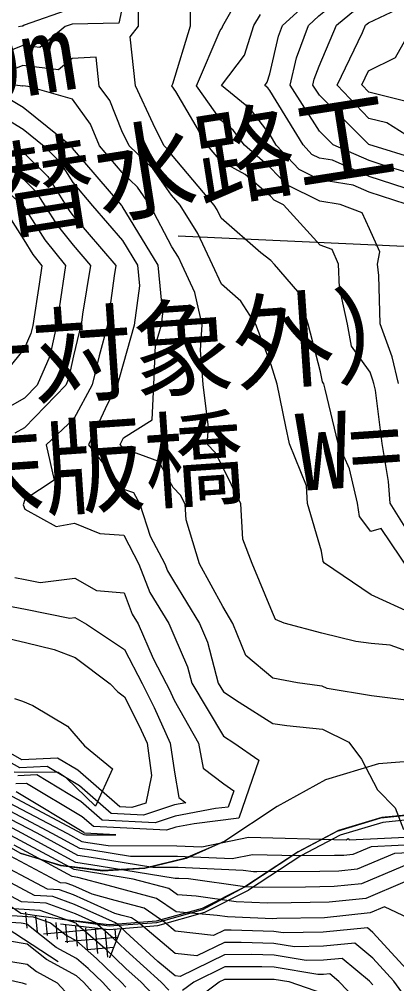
# Model space of a CAD drawing. Extents: x 42655 to 43811, y -141820 to -141156.
# Drawn here: x 43377.7 to 43416.6, y -141535.6 to -141436.2 of the extents above; entities that cross this region are included whole.
import ezdxf

# ---------------------------------------------------------------- set-up
doc = ezdxf.new("R2010")
doc.units = 0
for name, color, linetype in [('D-STR-HTXT', 7, 'Continuous'), ('ZE_HICN', 7, 'Continuous'), ('ZE_LWCN', 7, 'Continuous'), ('現況道路ﾊｯﾁ', 7, 'Continuous'), ('追加___', 7, 'Continuous'), ('追加____', 7, 'Continuous')]:
    doc.layers.add(name, color=color, linetype=linetype)

msp = doc.modelspace()

# ---------------------------------------------------------------- linework, layer by layer
at = {"layer": 'D-STR-HTXT'}
msp.add_line((43460.61, -141461.583), (43394.093, -141458.563), dxfattribs=at)
at = {"layer": 'ZE_HICN'}
for points in [[(43417.581, -141455.256), (43413.771, -141454.015), (43412.129, -141453.296), (43408.677, -141452.727), (43406.569, -141451.692), (43404.205, -141449.157), (43403.567, -141448.11), (43401.541, -141445.445), (43398.544, -141443.021), (43400.938, -141439.872), (43401.904, -141436.842), (43402.559, -141435.689)], [(43417.427, -141444.612), (43413.723, -141443.706), (43413.007, -141442.952), (43413.712, -141441.487), (43416.481, -141440.135), (43418.363, -141436.764)], [(43419.086, -141501.859), (43415.917, -141500.734), (43413.991, -141500.551), (43412.396, -141500.351), (43408.898, -141499.491), (43405.026, -141498.454), (43404.103, -141498.096), (43403.8, -141497.372), (43401.711, -141492.307), (43400.762, -141489.785), (43400.553, -141486.15), (43398.64, -141482.237), (43397.912, -141480.874), (43397.064, -141480.004), (43397.208, -141478.291), (43396.662, -141473.843), (43396.403, -141470.323), (43396.567, -141467.681), (43395.799, -141464.346), (43394.491, -141461.528), (43394.114, -141460.726), (43393.445, -141459.65), (43391.219, -141455.381), (43389.886, -141453.5), (43388.321, -141451.982), (43385.984, -141449.243), (43385.077, -141446.984), (43383.197, -141444.428), (43378.629, -141443.115), (43378.102, -141443.054), (43378.063, -141443.07), (43373.011, -141442.378)], [(43373.051, -141450.893), (43378.161, -141455.442), (43380.372, -141458.936), (43382.495, -141461.584), (43381.836, -141465.979), (43381.562, -141467.752), (43380.855, -141470.93), (43379.55, -141473.924), (43378.254, -141475.272), (43375.527, -141476.793)], [(43375.078, -141496.4), (43378.357, -141497.016), (43382.932, -141497.931), (43383.449, -141497.867), (43384.654, -141498.55), (43388.553, -141501.18), (43390.382, -141504.686), (43391.622, -141507.16), (43393.281, -141510.835), (43393.701, -141513.826), (43394.165, -141516.447), (43394.875, -141516.99), (43393.727, -141517.203), (43390.518, -141518.257), (43387.183, -141518.093)], [(43387.183, -141518.093), (43383.918, -141515.236), (43380.606, -141513.247), (43377.785, -141513.378), (43374.206, -141511.387)], [(43419.376, -141522.067), (43416.374, -141522.217), (43412.529, -141523.829), (43410.657, -141524.021), (43408.703, -141524.061), (43402.203, -141524.119), (43401.87, -141524.106), (43400.778, -141523.953), (43394.093, -141523.671), (43391.478, -141523.668), (43385.566, -141522.703), (43383.764, -141522.409), (43379.552, -141520.134), (43375.942, -141518.216)], [(43417.69, -141537.263), (43416.312, -141535.377), (43414.145, -141533.013), (43412.294, -141531.466), (43409.051, -141531.778), (43406.086, -141531.834), (43403.961, -141531.479), (43400.6, -141531.381), (43398.872, -141531.385), (43396.014, -141532.781), (43393.789, -141532.529), (43389.992, -141529.339), (43389.298, -141528.86), (43388.338, -141528.603), (43387.564, -141528.396), (43383.321, -141526.491), (43381.864, -141525.967), (43380.617, -141525.896), (43374.511, -141522.658)], [(43388.728, -141538.205), (43386.327, -141535.519), (43384.817, -141534.076), (43383.615, -141533.027), (43381.532, -141531.896), (43378.51, -141529.496), (43377.918, -141529.396), (43373.93, -141529.168)]]:
    msp.add_lwpolyline(points, dxfattribs=at)
at = {"layer": 'ZE_LWCN'}
for points in [[(43418.852, -141452.344), (43415.616, -141451.352), (43413.756, -141450.746), (43410.061, -141449.129), (43408.653, -141447.725), (43405.616, -141442.987), (43406.275, -141440.147), (43407.531, -141436.815), (43408.597, -141435.832), (43411.143, -141433.732), (43413.666, -141431.731), (43414.326, -141431.421), (43415.421, -141430.615), (43418.731, -141426.797)], [(43418.844, -141450.674), (43413.748, -141449.111), (43408.636, -141444.012), (43407.971, -141442.976), (43408.116, -141442.355), (43408.622, -141441.012), (43410.398, -141436.802), (43412.356, -141435.186), (43413.677, -141434.138), (43415.771, -141433.156), (43418.751, -141430.962)], [(43419.035, -141491.049), (43415.947, -141486.077), (43415.758, -141483.843), (43415.095, -141479.918), (43414.421, -141474.429), (43414.248, -141473.76), (43414.161, -141473.399), (43413.859, -141472.577), (43411.95, -141469.905), (43411.529, -141467.61), (43410.706, -141463.844), (43410.62, -141461.452), (43409.96, -141459.942), (43408.709, -141459.473), (43404.94, -141455.316), (43403.988, -141454.849), (43403.597, -141454.429), (43400.999, -141452.201), (43398.492, -141450.823), (43397.105, -141449.19), (43393.846, -141443.621), (43393.443, -141443.045), (43393.527, -141442.85), (43395.346, -141436.873), (43395.328, -141433.143)], [(43416.805, -141473.748), (43416.137, -141470.982), (43414.893, -141467.594), (43414.777, -141462.601), (43414.634, -141461.433), (43414.856, -141460.153), (43413.789, -141457.805), (43413.063, -141456.147), (43410.777, -141455.288), (43408.688, -141454.943), (43405.279, -141453.27), (43403.583, -141451.452), (43400.925, -141449.172), (43399.753, -141447.631), (43398.472, -141446.595), (43395.974, -141443.033), (43398.428, -141437.324), (43398.612, -141437.082), (43398.683, -141436.857), (43400.65, -141433.399)], [(43417.483, -141453.592), (43413.764, -141452.381), (43409.988, -141450.728), (43408.667, -141450.51), (43407.86, -141450.114), (43406.955, -141449.144), (43403.546, -141443.545), (43403.328, -141443.259), (43403.007, -141443), (43403.264, -141442.662), (43403.537, -141441.804), (43404.434, -141437.938), (43404.853, -141436.828), (43408.586, -141433.387)], [(43388.242, -141435.309), (43387.974, -141436.576), (43383.16, -141436.69), (43382.448, -141436.934), (43379.843, -141439.078), (43378.082, -141438.876), (43375.453, -141439.938)], [(43383.153, -141435.085), (43378.22, -141436.776), (43378.073, -141436.879), (43378.022, -141436.893), (43377.654, -141436.957)], [(43419.052, -141494.71), (43415.018, -141488.704), (43413.937, -141489.021), (43412.79, -141487.472), (43412.584, -141486.093), (43411.746, -141482.551), (43410.573, -141479.94), (43409.228, -141474.327), (43409.112, -141473.784), (43408.956, -141473.566), (43408.771, -141472.553), (43407.489, -141467.629), (43406.436, -141464.252), (43404.022, -141461.483), (43403.628, -141461.074), (43402.607, -141460.257), (43398.519, -141456.701), (43398.113, -141455.835), (43397.811, -141455.349), (43393.4, -141450.13), (43393.048, -141449.633), (43392.613, -141449.211), (43391.52, -141446.957), (43389.711, -141443.062), (43389.16, -141437.999), (43390.001, -141436.898), (43389.991, -141434.777)], [(43418.835, -141448.916), (43415.588, -141446.862), (43413.735, -141446.409), (43410.463, -141442.964), (43413.073, -141437.541), (43413.391, -141436.788), (43413.569, -141436.641), (43413.689, -141436.546), (43417.217, -141434.89)], [(43418.348, -141497.522), (43413.968, -141495.552), (43409.151, -141492.272), (43409.015, -141492.089), (43408.858, -141491.041), (43407.407, -141486.117), (43407.319, -141484.292), (43405.559, -141479.964), (43405.174, -141478.191), (43404.307, -141473.807), (43403.679, -141471.807), (43402.098, -141467.655), (43400.549, -141465.252), (43398.552, -141463.494), (43397.631, -141461.513), (43396.114, -141458.28), (43394.302, -141455.366), (43393.42, -141454.322), (43391.467, -141451.566), (43389.055, -141449.228), (43388.3, -141447.672), (43387.053, -141444.567), (43385.959, -141443.08), (43385.637, -141440.101), (43383.177, -141440.225), (43381.767, -141441.385), (43378.092, -141440.965), (43376.758, -141441.504)], [(43417.59, -141506.394), (43414.017, -141505.951), (43409.428, -141505.205), (43408.924, -141504.953), (43408.654, -141504.926), (43406.378, -141504.61), (43403.832, -141504.139), (43401.072, -141501.802), (43399.717, -141498.479), (43398.709, -141496.755), (43396.305, -141492.333), (43394.914, -141487.794), (43394.813, -141486.177), (43394.324, -141485.261), (43393.562, -141484.48), (43392.1, -141481.783), (43388.455, -141480.461), (43388.125, -141480.046), (43388.45, -141479.344), (43391.425, -141477.482), (43391.574, -141473.867), (43391.768, -141469.792), (43392.365, -141467.701), (43392.522, -141466.542), (43392.034, -141461.539), (43388.337, -141455.465), (43388.277, -141455.394), (43383.221, -141449.468), (43383.145, -141449.347), (43383.054, -141449.256), (43378.113, -141445.291), (43376.92, -141444.563)], [(43375.701, -141446.054), (43378.123, -141447.532), (43380.289, -141449.27), (43381.899, -141450.871), (43383.237, -141453.01), (43385.284, -141455.409), (43388.354, -141458.986), (43389.914, -141461.549), (43390.12, -141463.661), (43389.569, -141467.714), (43388.414, -141471.763), (43387.976, -141473.344), (43387.847, -141473.885), (43386.763, -141475.913), (43384.842, -141480.061), (43388.475, -141484.625), (43389.479, -141484.989), (43390.135, -141486.199), (43391.221, -141489.492), (43392.721, -141492.35), (43392.999, -141493.08), (43393.608, -141494.084), (43396.283, -141498.495), (43397.127, -141500.428), (43398.205, -141504.649), (43398.75, -141505.559), (43400.371, -141506.595), (43403.854, -141508.822), (43405.304, -141509.023), (43408.945, -141509.387), (43411.671, -141510.748), (43412.968, -141512.489), (43414.628, -141515.648), (43416.45, -141517.498), (43417.315, -141519.727)], [(43373.698, -141449.301), (43378.148, -141452.666), (43379.407, -141453.918), (43380.354, -141455.432), (43381.612, -141457.42), (43383.268, -141459.485), (43385.052, -141461.572), (43384.247, -141466.593), (43384.096, -141467.74), (43383.898, -141468.453), (43383.322, -141470.879), (43382.793, -141473.255), (43382.508, -141473.91), (43378.269, -141478.323), (43377.268, -141478.881)], [(43377.332, -141449.283), (43378.134, -141449.89), (43380.653, -141452.395), (43382.547, -141455.422), (43382.852, -141455.903), (43383.253, -141456.404), (43387.661, -141461.56), (43387.49, -141462.627), (43386.817, -141467.727), (43385.937, -141470.898), (43385.224, -141473.897), (43383.353, -141477.4), (43380.48, -141480.082), (43381.304, -141483.724), (43378.304, -141485.719), (43378.126, -141486.256), (43378.308, -141486.711), (43381.537, -141488.502), (43383.403, -141488.132), (43386.013, -141489.227), (43388.497, -141489.391), (43390.057, -141492.362), (43391.179, -141495.305), (43393.123, -141498.51), (43393.634, -141499.682), (43395.062, -141502.953), (43395.498, -141504.662), (43398.772, -141510.124), (43399.835, -141510.804), (43402.392, -141512.584), (43400.344, -141518.582), (43395.738, -141519.152), (43393.842, -141519.503), (43392.895, -141519.814), (43385.366, -141519.443)], [(43376.005, -141455.452), (43378.177, -141458.944), (43379.132, -141460.452), (43380.049, -141461.596), (43379.764, -141463.494), (43379.104, -141467.763), (43378.917, -141468.604), (43378.23, -141470.179), (43375.151, -141473.945)], [(43377.25, -141493.745), (43378.343, -141493.95), (43379.867, -141494.255), (43383.43, -141493.812), (43385.662, -141495.079), (43388.526, -141495.344), (43389.36, -141497.531), (43389.963, -141498.525), (43391.531, -141502.119), (43392.864, -141504.674), (43393.164, -141505.274), (43393.666, -141506.385), (43396.201, -141510.821), (43396.657, -141513.399), (43398.795, -141515.033), (43399.811, -141515.741), (43399.236, -141517.423), (43397.944, -141517.583), (43393.784, -141518.353), (43391.707, -141519.036), (43386.274, -141518.768)], [(43373.945, -141499.407), (43378.373, -141500.444), (43381.31, -141501.176), (43383.469, -141501.989), (43387.093, -141504.702), (43387.883, -141505.534), (43388.576, -141506.047), (43390.08, -141509.046), (43390.892, -141510.846), (43391.359, -141514.168), (43390.757, -141517.01), (43389.329, -141517.479), (43388.092, -141517.418)], [(43377.227, -141506.246), (43377.73, -141506.39), (43378.064, -141506.491), (43379.114, -141506.947), (43382.704, -141509.085), (43384.456, -141511.121), (43387.333, -141513.481), (43385.582, -141517.334), (43382.568, -141514.424)], [(43388.092, -141517.418), (43383.768, -141513.635), (43381.674, -141512.377), (43377.999, -141512.548), (43375.621, -141511.225)], [(43382.568, -141514.424), (43381.718, -141513.855), (43377.185, -141513.843)], [(43386.274, -141518.768), (43384.067, -141516.837), (43379.538, -141514.117), (43377.571, -141514.208)], [(43385.366, -141519.443), (43384.217, -141518.438), (43378.469, -141514.986), (43377.357, -141515.038)], [(43376.973, -141516.312), (43384.246, -141520.175), (43384.362, -141520.238), (43384.412, -141520.246), (43384.576, -141520.273), (43387.657, -141520.276), (43384.457, -141520.118), (43384.367, -141520.039), (43377.401, -141515.856)], [(43376.63, -141516.947), (43382.681, -141520.161), (43384.163, -141520.962), (43384.797, -141521.065), (43386.877, -141521.405), (43393.95, -141521.412), (43396.521, -141521.52), (43401.335, -141520.517), (43411.41, -141520.804), (43411.603, -141520.679), (43411.711, -141520.789), (43411.723, -141520.821), (43419.699, -141520.422)], [(43419.538, -141521.245), (43413.991, -141521.522), (43412.082, -141522.322), (43411.153, -141522.417), (43410.183, -141522.437), (43406.27, -141522.472), (43401.755, -141522.343), (43399.662, -141522.779), (43394.022, -141522.541), (43389.177, -141522.536), (43385.182, -141521.884), (43383.964, -141521.685), (43381.117, -141520.147), (43376.286, -141517.581)], [(43418.757, -141522.913), (43412.975, -141525.336), (43410.16, -141525.624), (43407.222, -141525.684), (43402.748, -141525.724), (43400.973, -141525.655), (43395.15, -141524.842), (43394.164, -141524.8), (43393.779, -141524.8), (43385.951, -141523.522), (43383.565, -141523.133), (43377.988, -141520.12), (43375.598, -141518.85)], [(43417.457, -141525.152), (43413.421, -141526.843), (43409.664, -141527.228), (43405.742, -141527.308), (43403.292, -141527.33), (43400.075, -141527.205), (43395.957, -141526.629), (43394.04, -141526.463), (43393.122, -141525.831), (43389.466, -141524.852), (43386.336, -141524.341), (43383.366, -141523.856), (43376.423, -141520.106)], [(43418.735, -141535.365), (43414.132, -141530.345), (43413.585, -141529.887), (43409.044, -141530.324), (43404.893, -141530.403), (43403.955, -141530.246), (43399.547, -141530.118), (43398.866, -141530.119), (43397.74, -141530.669), (43393.779, -141530.221), (43392.713, -141529.326), (43390.573, -141527.85), (43387.612, -141527.058), (43385.226, -141526.419), (43383.228, -141525.522), (43382.542, -141525.275), (43381.954, -141525.242), (43374.713, -141521.402)], [(43418.467, -141529.204), (43415.349, -141527.729), (43413.868, -141528.35), (43409.168, -141528.832), (43404.261, -141528.932), (43403.836, -141528.935), (43399.177, -141528.754), (43398.109, -141528.605), (43393.875, -141528.238), (43391.848, -141526.84), (43386.886, -141525.512), (43383.771, -141524.679), (43383.167, -141524.58), (43377.194, -141521.354)], [(43414.158, -141535.755), (43413.808, -141535.389), (43411.004, -141533.044), (43409.058, -141533.231), (43407.279, -141533.265), (43403.967, -141532.711), (43401.653, -141532.644), (43398.878, -141532.65), (43394.287, -141534.892), (43393.8, -141534.837), (43392.012, -141533.335), (43388.691, -141530.319), (43388.241, -141529.889), (43387.624, -141529.35), (43383.414, -141527.46), (43381.186, -141526.659), (43379.28, -141526.551), (43374.309, -141523.914)], [(43393.116, -141536.324), (43392.332, -141535.49), (43388.7, -141532.192), (43387.385, -141530.936), (43385.58, -141529.359), (43383.508, -141528.429), (43380.509, -141527.351), (43377.942, -141527.205), (43374.106, -141525.171)], [(43353.374, -141535.674), (43353.643, -141535.009), (43355.522, -141529.501), (43357.123, -141528.248), (43358.148, -141527.446), (43362.092, -141529.47), (43363.248, -141530.034), (43363.721, -141530.035), (43368.342, -141531.117), (43370.923, -141532.472), (43373.437, -141532.576), (43376.66, -141533.301), (43378.53, -141533.618), (43379.496, -141534.385), (43381.625, -141535.541), (43383.638, -141537.769)], [(43376.605, -141527.859), (43379.831, -141528.043), (43383.521, -141529.369), (43383.568, -141529.406), (43383.598, -141529.423), (43386.529, -141531.983), (43388.708, -141534.065), (43390.289, -141535.5), (43392.162, -141537.491)], [(43375.267, -141528.514), (43379.154, -141528.735), (43380.951, -141529.381), (43382.55, -141530.651), (43383.607, -141531.225), (43385.673, -141533.029), (43388.269, -141535.509), (43388.718, -141536.012)], [(43388.738, -141540.398), (43384.385, -141535.528), (43383.961, -141535.123), (43383.624, -141534.829), (43380.514, -141533.14), (43378.52, -141531.557), (43374.661, -141530.903)], [(43357.319, -141535.655), (43358.177, -141533.533), (43360.129, -141531.854), (43363.264, -141533.383), (43366.517, -141533.389), (43368.354, -141533.819), (43369.381, -141534.358), (43373.446, -141534.526), (43378.03, -141535.558), (43378.431, -141535.687)], [(43414.174, -141539.105), (43410.648, -141535.404), (43409.713, -141534.622), (43409.064, -141534.684), (43408.471, -141534.696), (43403.973, -141533.944), (43402.706, -141533.907), (43398.884, -141533.915), (43395.692, -141535.474), (43394.522, -141536.345)], [(43395.519, -141537.541), (43398.315, -141535.462), (43398.89, -141535.181), (43403.759, -141535.17), (43403.978, -141535.176), (43405.485, -141535.428), (43409.074, -141536.649)]]:
    msp.add_lwpolyline(points, dxfattribs=at)
at = {"layer": '現況道路ﾊｯﾁ'}
for points in [[(43348.521, -141508.21), (43377.887, -141528.378)], [(43426.071, -141513.252), (43420.416, -141512.508), (43414.731, -141512.97), (43409.27, -141514.617), (43404.279, -141517.376)], [(43404.279, -141517.376), (43404.279, -141517.376), (43398.884, -141520.939), (43398.884, -141520.939)], [(43406.317, -141522.128), (43410.475, -141519.91), (43414.982, -141518.533), (43419.669, -141518.051), (43424.362, -141518.48)], [(43377.832, -141522.164), (43377.832, -141522.164), (43375.289, -141520.736), (43375.289, -141520.736)], [(43398.884, -141520.939), (43394.907, -141522.729), (43390.671, -141523.767), (43386.317, -141524.021), (43381.989, -141523.48), (43377.832, -141522.164)], [(43400.973, -141525.655), (43400.973, -141525.655), (43406.317, -141522.128), (43406.317, -141522.128)], [(43382.127, -141528.997), (43386.999, -141529.681), (43391.906, -141529.335), (43396.633, -141527.973), (43400.973, -141525.655)], [(43377.887, -141528.378), (43377.887, -141528.378), (43382.127, -141528.997), (43382.127, -141528.997)]]:
    msp.add_lwpolyline(points, dxfattribs=at)
at = {"layer": '追加___'}
for p, q in [((43378.549, -141529.931), (43378.403, -141528.256)), ((43379.585, -141530.302), (43379.438, -141528.612)), ((43380.622, -141530.673), (43380.473, -141528.966)), ((43386.266, -141529.997), (43380.21, -141530.526)), ((43381.658, -141531.045), (43381.507, -141529.316)), ((43382.694, -141531.416), (43382.534, -141529.578)), ((43383.73, -141531.787), (43383.552, -141529.741)), ((43384.767, -141532.158), (43384.567, -141529.867)), ((43385.803, -141532.53), (43385.578, -141529.957)), ((43386.839, -141532.901), (43386.587, -141530.01)), ((43387.698, -141531.237), (43387.592, -141530.028)), ((43387.843, -141530.863), (43382.463, -141531.333)), ((43387.44, -141531.902), (43384.716, -141532.14)), ((43387.037, -141532.941), (43386.968, -141532.947))]:
    msp.add_line(p, q, dxfattribs=at)
at = {"layer": '追加____'}
for p, q in [((43404.279, -141517.376), (43398.884, -141520.939)), ((43381.734, -141533.375), (43364.12, -141521.895)), ((43406.467, -141522.029), (43400.973, -141525.655)), ((43406.741, -141522.447), (43401.347, -141526.01)), ((43388.169, -141530.022), (43387.027, -141532.968))]:
    msp.add_line(p, q, dxfattribs=at)
for points in [[(43348.493, -141508.189), (43377.887, -141528.378)], [(43426.071, -141513.252), (43420.416, -141512.508), (43414.731, -141512.97), (43409.27, -141514.617), (43404.279, -141517.376)], [(43424.362, -141518.48), (43419.714, -141518.051), (43415.07, -141518.516), (43410.6, -141519.858), (43406.467, -141522.029)], [(43424.269, -141518.971), (43419.716, -141518.551), (43415.167, -141519.006), (43410.789, -141520.321), (43406.741, -141522.447)], [(43377.832, -141522.164), (43381.997, -141523.422), (43386.317, -141523.932), (43390.661, -141523.679), (43394.893, -141522.671), (43398.884, -141520.939)], [(43381.968, -141529.471), (43386.974, -141530.045), (43391.997, -141529.643), (43396.849, -141528.281), (43401.347, -141526.01)], [(43382.127, -141528.997), (43386.993, -141529.55), (43391.875, -141529.162), (43396.593, -141527.847), (43400.973, -141525.655)]]:
    msp.add_lwpolyline(points, dxfattribs=at)

# ---------------------------------------------------------------- texts
at = {"layer": 'D-STR-HTXT'}
for s, height, rotation, p in [('L=57.0m', 7.9662, 8.88319, (43346.373, -141449.157)), ('付替水路工 5.0×2.0', 7.96621, 8.88319, (43365.695, -141459.745)), ('（設計対象外）', 7.9662, 3.89574, (43348.338, -141477.236)), ('床版橋 W=3.0m L=9.0m', 7.96621, 3.89574, (43370.163, -141487.316))]:
    msp.add_text(s, height=height, rotation=rotation, dxfattribs=at).set_placement(p)

doc.saveas('drawing.dxf')
